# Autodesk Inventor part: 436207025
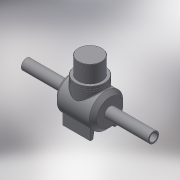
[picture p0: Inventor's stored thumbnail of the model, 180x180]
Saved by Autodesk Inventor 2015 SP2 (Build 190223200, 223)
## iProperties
Created: 2017-08
Part Number: 436207025
Material: Generic
Description: PLASSON PE BALL VALVE 25
Document SubType Name: Modeling
Designer: Кирилл
Density: 1 g/cm^3
Appearance: Default
Author: Кирилл
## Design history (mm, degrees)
derived "436207.ipt"
feature "Solid1::436207.ipt"
feature "Solid2::436207.ipt"
tag "TaggingFeature1"
body "Solid1"
other parameters: "d1" = 25, "d3" = 103, "d5" = 18.75, "d6" = 9, "d8" = 94, "d11" = 56, "d12" = 0.7, "d13" = 4, "d14" = 4, "d16" = 100 deg, "d17" = 32, "d18" = 6.4, "d20" = 65, "d21" = 0, "d22" = 0.7, "d26" = 3, "d28" = 0, "d29" = 1.4, "d_" = 25, "s_" = 3, "L_1" = 103, "B_" = 65, "H_" = 94
